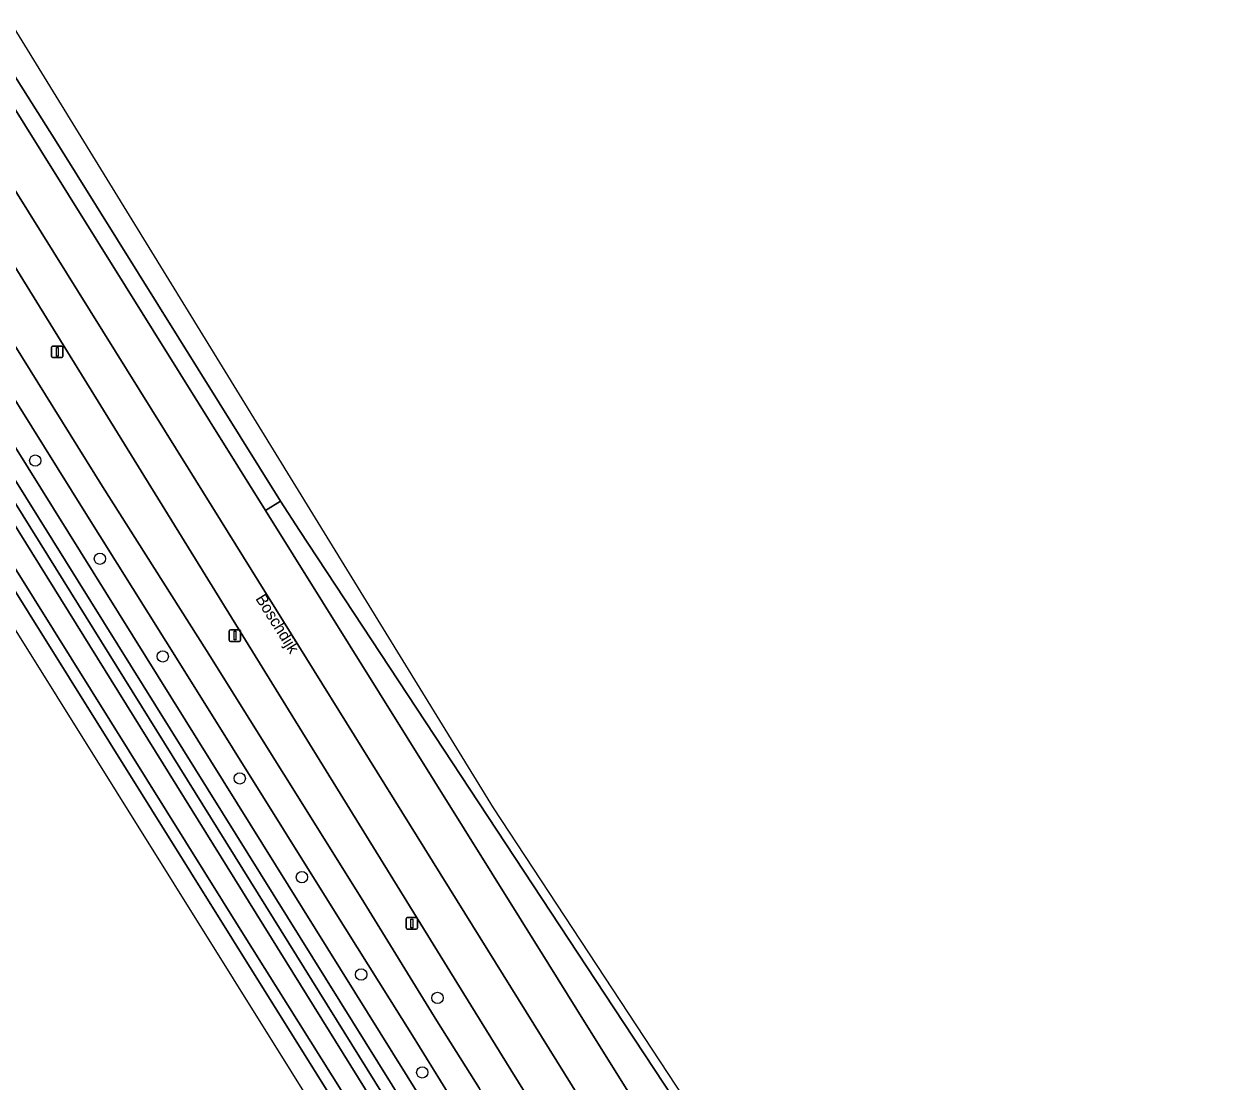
# Model space of a CAD drawing. Extents: x 158132 to 159664, y 385256 to 387218.
# Drawn here: x 159037.8 to 159142.4, y 386801.4 to 386893 of the extents above; entities that cross this region are included whole.
import ezdxf

# ---------------------------------------------------------------- set-up
doc = ezdxf.new("R2010")
doc.units = 0
for name, color, linetype in [('IMGEO_Berm_groen', 7, 'Continuous'), ('IMGEO_Berm_open', 7, 'Continuous'), ('IMGEO_Boom', 7, 'Continuous'), ('IMGEO_Fietspad_gesloten', 7, 'Continuous'), ('IMGEO_Gemengd_bos', 7, 'Continuous'), ('IMGEO_Hek', 7, 'Continuous'), ('IMGEO_Lichtmast', 7, 'Continuous'), ('IMGEO_Oever', 7, 'Continuous'), ('IMGEO_Openbare_ruimte_label', 7, 'Continuous'), ('IMGEO_Rijbaan_regionaal_gesloten', 7, 'Continuous'), ('IMGEO_Verkeerseiland_open', 7, 'Continuous'), ('IMGEO_Voetpad_open', 7, 'Continuous'), ('IMGEO_Waterloop', 7, 'Continuous')]:
    doc.layers.add(name, color=color, linetype=linetype)

msp = doc.modelspace()

# ---------------------------------------------------------------- linework, layer by layer
at = {"layer": 'IMGEO_Berm_groen'}
for points in [[(158939.72, 387012.31), (159014.42, 386892.71), (159073.19, 386798.43), (159076.42, 386793.24), (159080.78, 386786.08), (159081.37, 386784.78), (159081.94, 386783.14), (159080.78, 386787.36)], [(159078.06, 386794.8), (159075.09, 386799.57), (159071.45, 386805.45), (159064.7, 386816.23), (159051.47, 386837.43), (159043.05, 386850.88), (159031.61, 386869.16), (159021.52, 386885.26), (159009.4, 386904.75), (159000, 386919.62), (158996.04, 386925.89), (158983.07, 386946.51), (158968.82, 386969.55), (158956.19, 386989.91)], [(159097.62, 386774.07), (159079.97, 386802.5), (159076.51, 386808.08), (159024.95, 386891.53)], [(159033.41, 386870.98), (159044.62, 386852.96), (159053.63, 386838.77), (159067, 386817.36), (159073.57, 386806.72), (159077.25, 386800.87)]]:
    msp.add_lwpolyline(points, dxfattribs=at)
at = {"layer": 'IMGEO_Berm_open'}
msp.add_lwpolyline([(158965.55, 387000), (158975.98, 386983.29), (158989.71, 386961.33), (159000, 386944.85), (159004.62, 386937.46), (159024.03, 386906.51), (159039.3, 386882.04), (159058.74, 386850.89), (159060.03, 386851.7), (159040.61, 386882.82), (159031.34, 386897.46), (159016.97, 386920.42), (159000, 386947.66), (158978.52, 386982.01), (158967.35, 387000)], dxfattribs=at)
at = {"layer": 'IMGEO_Boom'}
for centre in [(159038.8, 386855.21), (159044.4, 386846.72), (159049.84, 386838.27), (159056.5, 386827.71), (159061.88, 386819.16), (159067.01, 386810.74), (159073.62, 386808.71), (159072.3, 386802.27)]:
    msp.add_circle(centre, 0.489, dxfattribs=at)
at = {"layer": 'IMGEO_Fietspad_gesloten'}
for points in [[(158943.64, 387014.74), (158943.29, 387014.52), (158941.33, 387013.3), (158945.18, 387007.28), (158949.85, 387000), (158956.19, 386989.91), (158968.82, 386969.55), (158983.07, 386946.51), (158996.04, 386925.89), (159000, 386919.62), (159009.4, 386904.75), (159021.52, 386885.26), (159031.61, 386869.16), (159043.05, 386850.88), (159051.47, 386837.43), (159064.7, 386816.23), (159071.45, 386805.45), (159075.09, 386799.57), (159078.06, 386794.8)], [(159126.06, 386713.85), (159124.29, 386716.67), (159123.71, 386717.56), (159116.57, 386729), (159103.46, 386750), (159087.41, 386775.7), (159087.28, 386775.92), (159086.31, 386777.79), (159085.51, 386779.75), (159084.88, 386781.77), (159082.05, 386791.86), (159081.53, 386793.42), (159080.87, 386794.93), (159080.27, 386796.04), (159077.25, 386800.87), (159073.57, 386806.72), (159067, 386817.36), (159053.63, 386838.77), (159044.62, 386852.96), (159033.41, 386870.98)]]:
    msp.add_lwpolyline(points, dxfattribs=at)
at = {"layer": 'IMGEO_Gemengd_bos'}
for points in [[(159000, 386911.16), (159068.85, 386800.41)], [(158947.18, 386801.12), (159066.06, 386794.15), (159080.08, 386771.7), (159078.25, 386775.14), (159074.93, 386782.92), (159071.31, 386789.11), (159067.59, 386795.06), (159055.81, 386813.89), (159031.24, 386853.2), (159000, 386903.6)], [(159071.89, 386797.65), (159013.13, 386891.92)]]:
    msp.add_lwpolyline(points, dxfattribs=at)
at = {"layer": 'IMGEO_Hek'}
msp.add_lwpolyline([(159000, 386899.91), (159066.06, 386794.15)], dxfattribs=at)
at = {"layer": 'IMGEO_Lichtmast'}
for p, q in [((159040.31, 386865.13), (159041.1, 386865.13)), ((159041.1, 386865.13), (159040.31, 386865.13)), ((159040.21, 386864.23), (159040.21, 386865.03)), ((159040.21, 386865.03), (159040.21, 386864.23)), ((159041.1, 386864.13), (159040.31, 386864.13)), ((159040.31, 386864.13), (159041.1, 386864.13)), ((159041.2, 386865.03), (159041.2, 386864.23)), ((159041.2, 386864.23), (159041.2, 386865.03)), ((159055.59, 386839.67), (159055.59, 386840.47)), ((159055.59, 386840.47), (159055.59, 386839.67)), ((159055.69, 386840.57), (159056.48, 386840.57)), ((159056.48, 386840.57), (159055.69, 386840.57)), ((159056.58, 386840.47), (159056.58, 386839.67)), ((159056.58, 386839.67), (159056.58, 386840.47)), ((159056.48, 386839.57), (159055.69, 386839.57)), ((159055.69, 386839.57), (159056.48, 386839.57)), ((159070.9, 386814.77), (159070.9, 386815.57)), ((159070.9, 386815.57), (159070.9, 386814.77)), ((159071, 386815.67), (159071.78, 386815.67)), ((159071.78, 386815.67), (159071, 386815.67)), ((159071.88, 386815.57), (159071.88, 386814.77)), ((159071.88, 386814.77), (159071.88, 386815.57)), ((159071.78, 386814.67), (159071, 386814.67)), ((159071, 386814.67), (159071.78, 386814.67))]:
    msp.add_line(p, q, dxfattribs=at)
for points in [[(159040.63, 386865.01), (159040.78, 386865.01), (159040.78, 386864.26), (159040.63, 386864.26), (159040.63, 386865.01)], [(159056.01, 386840.44), (159056.16, 386840.44), (159056.16, 386839.69), (159056.01, 386839.69), (159056.01, 386840.44)], [(159071.32, 386815.54), (159071.47, 386815.54), (159071.47, 386814.79), (159071.32, 386814.79), (159071.32, 386815.54)]]:
    msp.add_lwpolyline(points, dxfattribs=at)
for centre, start, end in [((159040.31, 386865.03), 90, 180), ((159040.31, 386865.03), 90, 180), ((159041.1, 386865.03), 0, 90), ((159041.1, 386865.03), 360, 90), ((159040.31, 386864.23), 180, 270), ((159040.31, 386864.23), 180, 270), ((159041.1, 386864.23), 270, 0), ((159041.1, 386864.23), 270, 0), ((159055.69, 386840.47), 90, 180), ((159055.69, 386840.47), 90, 180), ((159056.48, 386840.47), 0, 90), ((159056.48, 386840.47), 360, 90), ((159055.69, 386839.67), 180, 270), ((159055.69, 386839.67), 180, 270), ((159056.48, 386839.67), 270, 0), ((159056.48, 386839.67), 270, 0), ((159071, 386815.57), 90, 180), ((159071, 386815.57), 90, 180), ((159071.78, 386815.57), 0, 90), ((159071.78, 386815.57), 360, 90), ((159071, 386814.77), 180, 270), ((159071, 386814.77), 180, 270), ((159071.78, 386814.77), 270, 0), ((159071.78, 386814.77), 270, 0)]:
    msp.add_arc(centre, 0.1, start, end, dxfattribs=at)
at = {"layer": 'IMGEO_Oever'}
for points in [[(159068.85, 386800.41), (159000, 386911.16)], [(158999.12, 386910.6), (159067.96, 386799.86)], [(159031.24, 386853.2), (159055.81, 386813.89), (159067.59, 386795.06), (159071.31, 386789.11), (159074.93, 386782.92), (159078.25, 386775.14), (159080.08, 386771.7), (159084.23, 386763.92), (159093.2, 386750), (159095.49, 386746.45), (159100, 386739.67), (159110.54, 386721.95), (159111.51, 386722.6), (159100.89, 386740.23), (159096.36, 386747.02), (159094.08, 386750.57), (159085.13, 386764.45), (159081, 386772.19), (159079.19, 386775.59), (159075.87, 386783.39), (159072.21, 386789.65), (159068.47, 386795.61), (159056.69, 386814.44), (159032.13, 386853.75)]]:
    msp.add_lwpolyline(points, dxfattribs=at)
at = {"layer": 'IMGEO_Rijbaan_regionaal_gesloten'}
for points in [[(158967.35, 387000), (158978.52, 386982.01), (159000, 386947.66), (159016.97, 386920.42), (159031.34, 386897.46), (159040.61, 386882.82), (159060.03, 386851.7), (159061.67, 386849.16), (159088.88, 386807.86), (159097.59, 386794.63), (159098.72, 386792.91), (159104.7, 386783.36), (159116.43, 386764.6), (159125.54, 386750), (159140.14, 386726.61), (159142.37, 386727.98), (159078.47, 386825.15), (159022.01, 386917.02), (158943.79, 387040.77)], [(159019.18, 386907.28), (159052.05, 386854.56), (159076.66, 386814.97), (159097.37, 386781.66), (159106.44, 386765.8), (159113.12, 386754.13), (159118.54, 386745.29), (159125.95, 386732.99), (159132.72, 386721.99), (159135.47, 386723.71), (159125.43, 386739.97), (159111, 386764.22), (159103.51, 386777.86), (159100.94, 386783.31), (159086.49, 386806.42), (159083.26, 386811.59), (159058.74, 386850.89), (159039.3, 386882.04), (159024.03, 386906.51)], [(159024.95, 386891.53), (159076.51, 386808.08), (159079.97, 386802.5), (159097.62, 386774.07), (159101.27, 386768.38), (159121.03, 386734.56), (159129.88, 386720.22), (159132.72, 386721.99), (159125.95, 386732.99), (159118.54, 386745.29), (159113.12, 386754.13), (159106.44, 386765.8), (159097.37, 386781.66), (159076.66, 386814.97), (159052.05, 386854.56), (159019.18, 386907.28)]]:
    msp.add_lwpolyline(points, dxfattribs=at)
at = {"layer": 'IMGEO_Verkeerseiland_open'}
msp.add_lwpolyline([(159098.72, 386792.91), (159097.59, 386794.63), (159088.88, 386807.86), (159061.67, 386849.16), (159060.03, 386851.7), (159058.74, 386850.89), (159083.26, 386811.59), (159086.49, 386806.42), (159100.94, 386783.31), (159102.04, 386781.61), (159111.65, 386767.52), (159113.06, 386765.35), (159115.44, 386761.58), (159122.68, 386750), (159138.08, 386725.34), (159138.13, 386725.27)], dxfattribs=at)
at = {"layer": 'IMGEO_Voetpad_open'}
for points in [[(159073.19, 386798.43), (159014.42, 386892.71)], [(159013.13, 386891.92), (159071.89, 386797.65)]]:
    msp.add_lwpolyline(points, dxfattribs=at)
at = {"layer": 'IMGEO_Waterloop'}
for points in [[(159067.96, 386799.86), (158999.12, 386910.6)], [(159032.13, 386853.75), (159056.69, 386814.44), (159068.47, 386795.61)]]:
    msp.add_lwpolyline(points, dxfattribs=at)

# ---------------------------------------------------------------- texts
at = {"layer": 'IMGEO_Openbare_ruimte_label'}
msp.add_text('Boschdijk', height=1, rotation=302.0539, dxfattribs=at).set_placement((159057.83, 386843.27))

doc.saveas('drawing.dxf')
